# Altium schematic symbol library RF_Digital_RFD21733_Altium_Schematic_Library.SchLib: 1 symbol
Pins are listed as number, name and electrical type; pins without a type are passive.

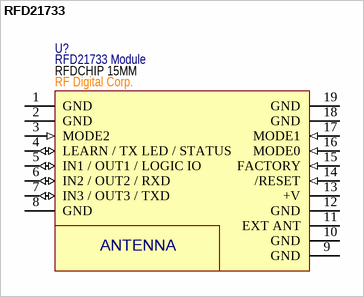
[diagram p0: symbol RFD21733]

## RFD21733
designator U?, comment RFD21733 Module  DistributorPN: RF Digital Corp.  PackageReference: RFDCHIP 15MM
Compliance Approved 2.4 GHz RF Transceiver Module with Built-In RFDP8 Application Protocol
footprint RFD21733 (2.4 GHz RF Transceiver Module)
pins: 1 GND (power), 2 GND (power), 3 MODE2 (in), 4 LEARN / TX LED / STATUS (io), 5 IN1 / OUT1 / LOGIC IO (io), 6 IN2 / OUT2 / RXD (io), 7 IN3 / OUT3 / TXD (io), 8 GND (power), 9 GND (power), 10 GND (power), 11 EXT ANT, 12 GND (power), 13 +V (power), 14 /RESET (in), 15 FACTORY (in), 16 MODE0 (in), 17 MODE1 (in), 18 GND (power), 19 GND (power)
